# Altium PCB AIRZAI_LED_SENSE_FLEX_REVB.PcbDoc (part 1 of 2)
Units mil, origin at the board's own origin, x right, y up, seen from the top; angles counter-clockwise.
Board outline 2713.44 x 4393.69 mil, 2 copper layers (Top Layer, Bottom Layer); 53 components, 36 nets, 162 pads, 79 vias.
Unrouted connection lines stored in the file: 83.
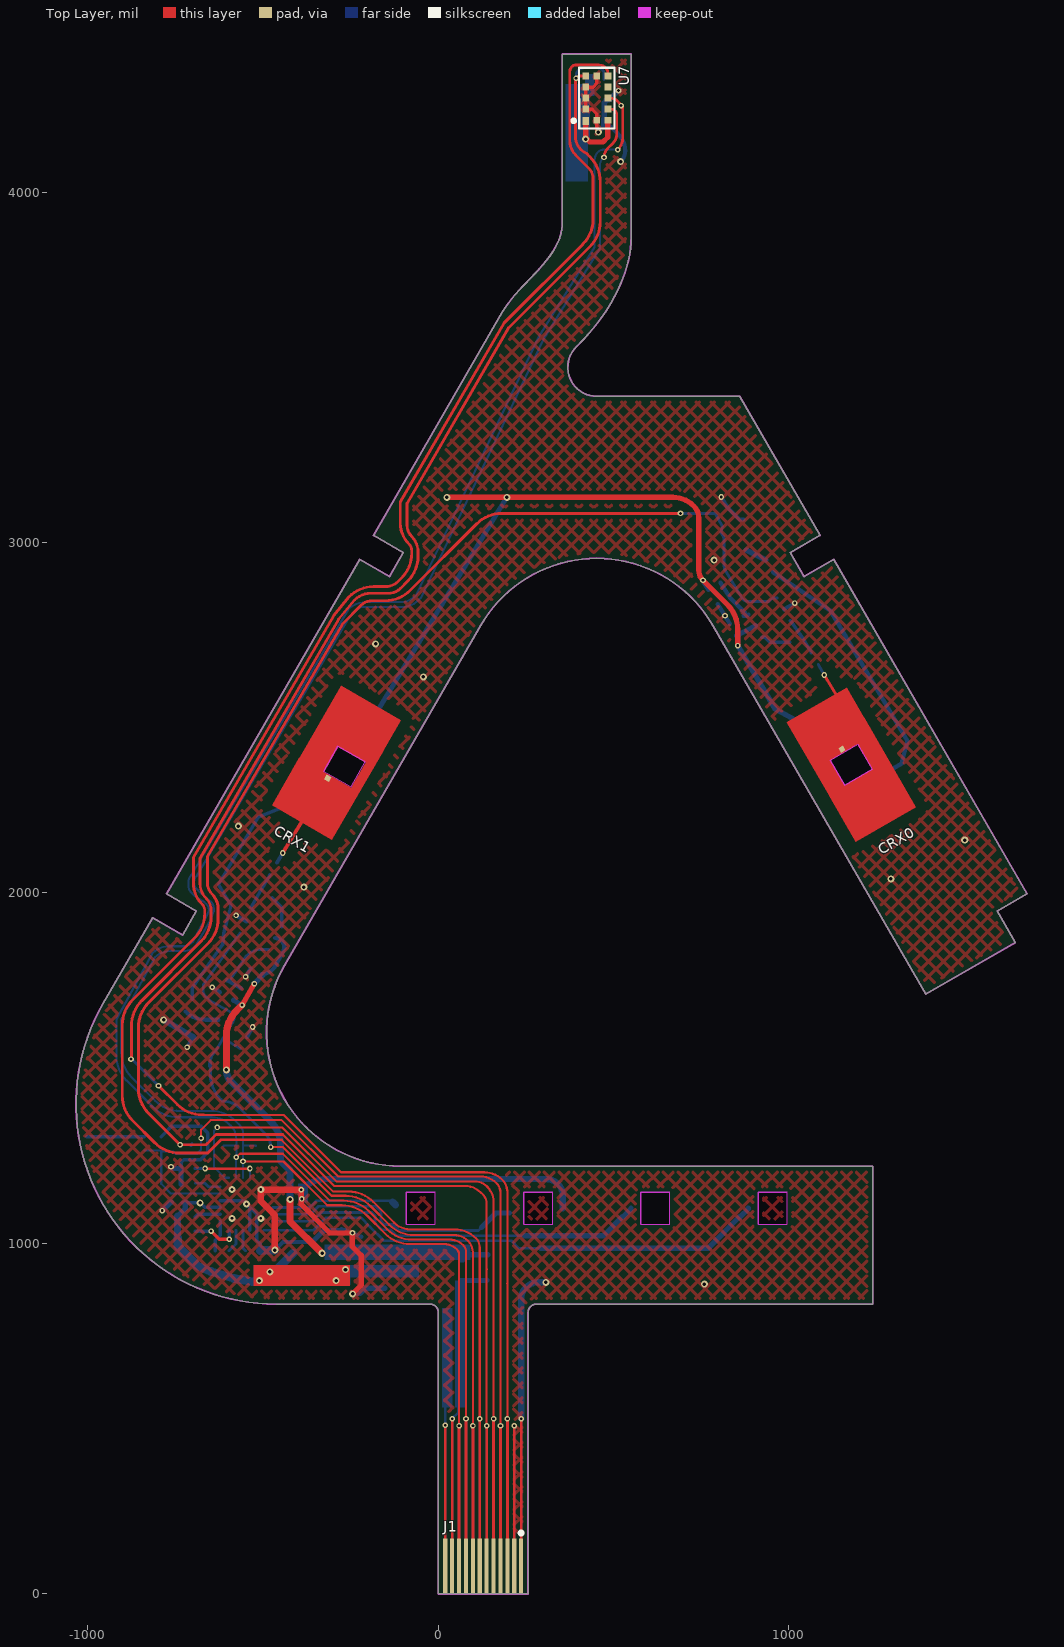
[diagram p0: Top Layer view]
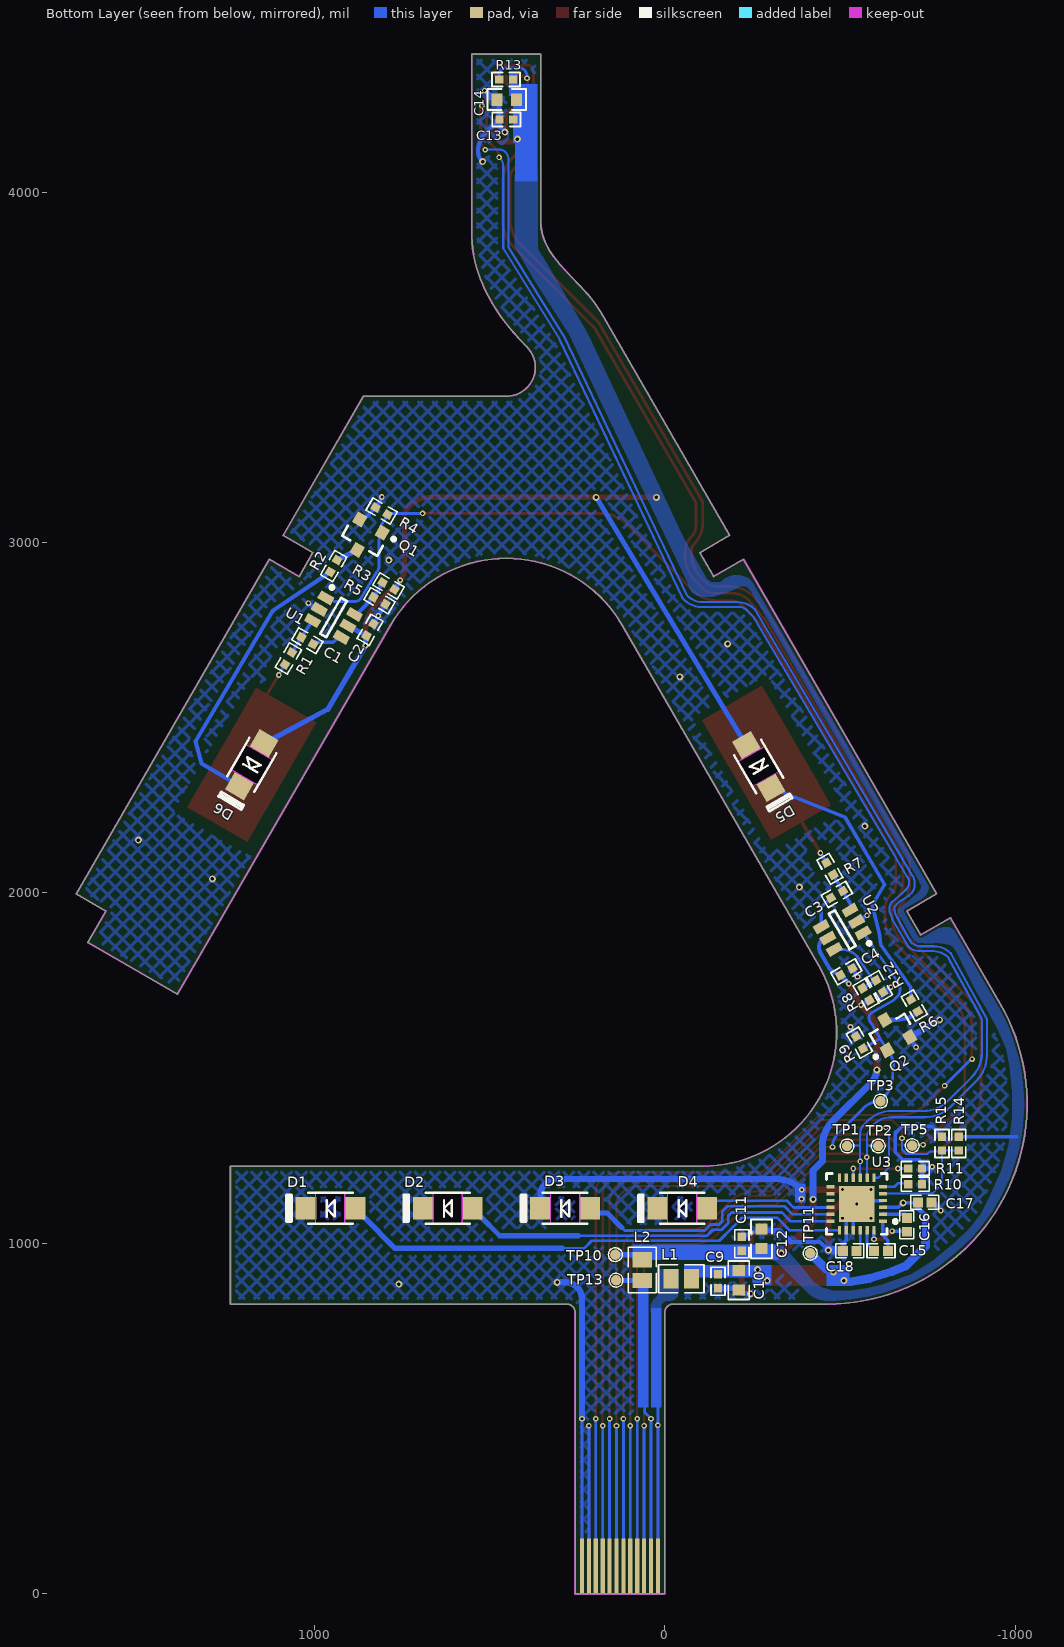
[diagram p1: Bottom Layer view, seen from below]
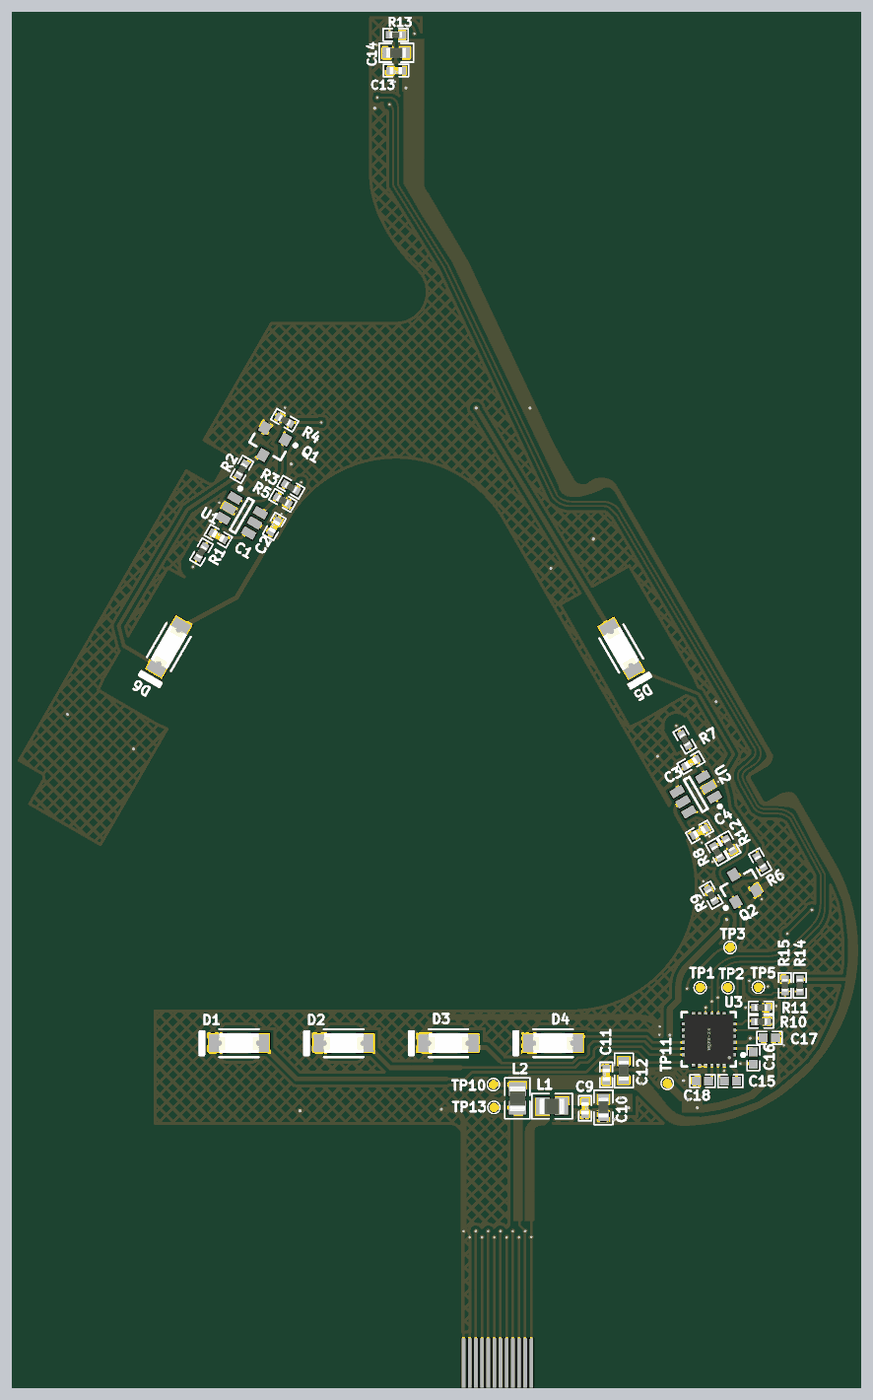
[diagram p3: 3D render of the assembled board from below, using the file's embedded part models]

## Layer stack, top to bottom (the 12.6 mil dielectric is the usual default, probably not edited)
Top Solder: solder mask 0.4, Solder Resist, Dk 3.5
Top Layer: signal copper 1.4
Dielectric 1: dielectric 12.6, FR-4, Dk 4.8
Bottom Layer: signal copper 1.4
Bottom Solder: solder mask 0.4, Solder Resist, Dk 3.5

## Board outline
-463,826.78 cw(c-462.98,1397.65) -957.36,1683.09 -815.14,1929.41 -729.91,1880.19 -690.53,1948.38 -775.77,1997.6 -224.58,2952.23 -139.35,2903.01 -99.97,2971.2 -185.21,3020.41 182.62,3657.47 cw(c465.09,3488.64) 220.1,3708.36 cw(c839.65,3165.01) 242.17,3732.54 264.96,3756.39 ccw(c-627.68,4615.35) 287.35,3780.27 ccw(c-93.59,4128.16) 308.19,3804.57 ccw(c73.79,3993.55) 326.37,3829.65 ccw(c158.18,3938.86) 340.75,3855.9 ccw(c204.05,3917.92) 350.2,3883.68 ccw(c222.06,3913.41) 353.61,3913.38 353.61,3952.75 353.61,4393.69 550.46,4393.69 550.46,3952.74 550.46,3874 cw(c239.31,3875.17) 542.24,3804.11 cw(c183.5,3887.15) 532.52,3769.79 cw(c138.88,3902.12) 519.55,3736.13 cw(c91.77,3922.61) 503.7,3703.33 cw(c24.31,3959.43) 464.84,3641.1 cw(c-49.74,4012.89) 394.16,3559.04 ccw(c452.02,3499.99) 452.02,3417.31 860.08,3417.3 1089.23,3020.38 1003.99,2971.17 1043.36,2902.98 1128.6,2952.19 1679.74,1997.53 1594.5,1948.32 1646.29,1858.61 1390.38,1711.31 782.73,2763.85 ccw(c452,2572.92) 121.28,2763.87 -439.1,1793.32 ccw(c-108.38,1602.36) -108.39,1220.47 1239.37,1220.44 1239.37,826.77 279.66,826.77 ccw(c279.78,802.89) 255.91,802.77 255.91,0 0,0 0,802.41 ccw(c-23.88,802.89) -23.39,826.77
cut-out: 912.59,1055.11 995.26,1055.11 995.26,1145.66 912.59,1145.66
cut-out: 577.94,1055.12 660.62,1055.12 660.62,1145.67 577.94,1145.67
cut-out: 243.3,1055.12 325.97,1055.12 325.97,1145.67 243.3,1145.67
cut-out: -91.36,1055.12 -8.68,1055.12 -8.68,1145.67 -91.36,1145.67
cut-out: 1159.59,2307.55 1118.49,2378.93 1196.97,2424.11 1238.06,2352.73
cut-out: -327.65,2347.93 -249.18,2302.74 -208.08,2374.12 -286.55,2419.3

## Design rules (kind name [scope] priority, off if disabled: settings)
Clearance Clearance_Board_Cutout_Electrodes [(InComponent('CRX0') OR InComponent('CRX1')) vs OnLayer('Multi-Layer')] p1: gap=0 ignorepadtopadclearanceinfootprint=FALSE
Clearance Clearance_Board_Cutout_Diodes [(InComponent('D1') OR InComponent('D2') OR InComponent('D3') OR InComponent('D4') OR InComponent('D5') OR InComponent('D6')) vs OnLayer('Multi-Layer')] p2: gap=0 ignorepadtopadclearanceinfootprint=FALSE
Clearance Clearance_Keepout [(OnLayer('Keep-Out Layer')) vs (InComponent('D1') OR InComponent('D2') OR InComponent('D3') OR InComponent('D4') OR InComponent('D5') OR InComponent('D6') OR InComponent('CRX0') OR InComponent('CRX1') OR InComponent('J1'))] p3: gap=0 ignorepadtopadclearanceinfootprint=FALSE
Clearance Clearance_GND_POLY_ELECTRODE [(InComponent('CRX0') OR InComponent('CRX1') OR InComponent('CRX2') OR InNet('NetCRX0_1') OR InNet('NetCRX1_1') OR InNet('NetCRX2_1') OR InNet('NetR4_2') OR InNet('NetR2_1') OR InNet('NetR1_1')) vs (InNet('GND') AND InPolygon)] p4: gap=30 ignorepadtopadclearanceinfootprint=FALSE
Clearance Clearance_POLYGON_KEEPOUT [(OnLayer('Keep-Out Layer')) vs (InNet('GND') AND InPolygon)] p5: gap=10 ignorepadtopadclearanceinfootprint=FALSE
Clearance Clearance_GND_POLY_REST [All vs (InNet('GND') AND InPolygon)] p6: gap=10 ignorepadtopadclearanceinfootprint=FALSE
Clearance [All] p7: gap=6 ignorepadtopadclearanceinfootprint=FALSE
MinimumSolderMaskSliver [All] p1: minsoldermaskwidth=1
PolygonConnect [All] p1: connectstyle=Direct reliefconductorwidth=10 reliefentries=4 polygonreliefangle="90 Angle" airgapwidth=10
RoomDefinition AIRZAI_LED_SENSE_FLEX_REVB [InComponentClass('AIRZAI_LED_SENSE_FLEX_REVB')] p1: confinementstyle=ConfineIn formatcopy=TRUE lockcomponents=FALSE outline -3892.14,-2713.97 10767.86,-2713.97 10767.86,6886.03 -3892.14,6886.03
RoutingVias [All] p1: holewidth=28 width=50 viastyle="Through Hole" minholewidth=8 minwidth=16 maxholewidth=28 maxwidth=50
SilkToSilkClearance [All] p1: silktosilkclearance=1
SilkToSolderMaskClearance [IsPad] p1: minsilkscreentomaskgap=2 clearancetoexposedcopper=TRUE
SolderMaskExpansion [All] p1: expansion=4
UnRoutedNet [All] p1: checkbadconnections=TRUE
Width [All] p1: maxlimit=100 minlimit=6 preferedwidth=10
26 further rules are at their usual default settings.

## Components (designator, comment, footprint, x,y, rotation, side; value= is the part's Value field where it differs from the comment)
C1 "22nF" 0402CAP 1020,2720 r210 bottom
C2 "0.1µF" 0402CAP 841,2751 r120 bottom
C3 "22nF" 0402CAP -491,1996 r330 bottom
C4 "0.1µF" 0402CAP -518.16,1775.08 r150 bottom
C9 "0.1µF" 0402CAP -152,892.17 r270 bottom
C10 "10µF" 0603 -211,895 r270 bottom
C11 "0.1µF" 0402CAP -220,999.22 r90 bottom
C12 "10µF" 0603 -276,1013 r90 bottom
C13 "0.1µF" 0402CAP 452.01,4207.25 r0 bottom
C14 "4.7µF" 0603 451,4264 r180 bottom
C15 "CAP 1uF 16V 0402(1005)" CAPC0402(1005)60_M -616.69,979 r0 bottom value=1uF
C16 "CAP 1uF 16V 0402(1005)" CAPC0402(1005)60_M -690.55,1053.06 r270 bottom value=1uF
C17 "CAP 1uF 16V 0402(1005)" CAPC0402(1005)60_M -741.73,1117.23 r0 bottom value=1uF
C18 "CAP 1uF 16V 0402(1005)" CAPC0402(1005)60_M -527.69,979 r0 bottom value=1uF
CRX0 "CONTACT POINT 1" "CONTACT_POINT_1CM _SQ - duplicate" 1178.28,2365.83 r300 top
CRX1 "CONTACT POINT 1" "CONTACT_POINT_1CM _SQ" -290.35,2372.21 r60 top
D1 "WHITE" LED1206_LTW-C230DS 953.93,1100.39 r0 bottom locked
D2 "WHITE" LED1206_LTW-C230DS 619.28,1100.4 r0 bottom locked
D3 "WHITE" LED1206_LTW-C230DS 284.63,1100.41 r0 bottom locked
D4 "WHITE" LED1206_LTW-C230DS -50.03,1100.42 r0 bottom
D5 "WHITE" LED1206_LTW-C230DS -267.86,2361.02 r240 bottom
D6 "WHITE" LED1206_LTW-C230DS 1178.28,2365.83 r300 bottom
J1 "FFC Pads" FFC_PADS 127.95,78.74 r0 top locked
L1 "CB2012T100KR" 0805 -47,899 r180 bottom value=10uH
L2 "CB2012T100KR" 0805 64,924 r90 bottom value=10uH
Q1 "NTR4003NT1G" SOT-23-3-NTR4003NT1G 858,3013 r300 bottom
Q2 "NTR4003NT1G" SOT-23-3-NTR4003NT1G -647,1604 r60 bottom
R1 "10k 0402(1005)" 0402 1074,2669 r300 bottom value=10k
R2 "100R 0402(1005)" 0402 944.64,2933 r300 bottom value=100
R3 "Jumper 0402(1005)" 0402 788.11,2876 r210 bottom value=0R
R4 "DNP 0402(1005)" 0402 808,3090 r30 bottom value=DNP
R5 "DNP 0402(1005)" 0402 814,2834 r210 bottom value=DNP
R6 "100R 0402(1005)" 0402 -712,1679.08 r60 bottom value=100
R7 "10k 0402(1005)" 0402 -471,2069 r60 bottom value=10k
R8 "Jumper 0402(1005)" 0402 -574.02,1711 r240 bottom value=0R
R9 "DNP 0402(1005)" 0402 -555.51,1573 r60 bottom value=DNP
R10 "Jumper 0402(1005)" 0402 -714.57,1168.99 r0 bottom value=0R
R11 "Jumper 0402(1005)" 0402 -714.57,1213.99 r0 bottom value=0R
R12 "DNP 0402(1005)" 0402 -613,1734 r240 bottom value=DNP
R13 "10k 0402(1005)" 0402 453,4321 r0 bottom value=10k
R14 "Jumper 0402(1005)" 0402 -838.76,1285 r270 bottom value=0R
R15 "DNP 0402(1005)" 0402 -790.88,1285 r90 bottom value=DNP
TP1 "Test Point" TP_0.9MM -520.09,1278 r90 bottom
TP2 "Test Point" TP_0.9MM -608.92,1278 r90 bottom
TP3 "Test Point" TP_0.9MM -615.68,1406 r90 bottom
TP5 "Test Point" TP_0.9MM -706,1279 r90 bottom
TP10 "Test Point" TP_0.9MM 141,968 r90 bottom
TP11 "Test Point" TP_0.9MM -415,972 r90 bottom
TP13 "Test Point" TP_0.9MM 139,895 r90 bottom
U1 "AT42QT1010-TSHR" SOT-23-6-AT42QT1010-TSHR 944.94,2785.89 r210 bottom
U2 "AT42QT1010-TSHR" SOT-23-6-AT42QT1010-TSHR -506.3,1895 r330 bottom
U3 "LP55231SQE/NOPB" WQFN-24-LP55231SQE/NOPB -547.74,1112.61 r0 bottom value="IC LED DRIVER RGLTR DIM 24WQFN"
U7 "VL53L0CXV0DH/1" VL53L0X 452,4268 r270 top

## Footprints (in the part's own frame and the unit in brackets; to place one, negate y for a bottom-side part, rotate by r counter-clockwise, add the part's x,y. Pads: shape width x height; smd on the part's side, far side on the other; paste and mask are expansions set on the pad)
0402 [mm] "Chip Resistor, Body 1.1x0.5mm, IPC High Density"
  rect 0.6x0.6 smd: 1(-0.5,0) 2(0.5,0)
  silkscreen extent -1.02,-0.51 1.02,0.51, body extent -0.5,-0.25 0.5,0.25, height 0.27
0402CAP [mm] "Chip Capacitor, Body 1.1x0.5mm, IPC High Density"
  rect 0.6x0.6 smd: 1(-0.5,0) 2(0.5,0)
  silkscreen extent -1.02,-0.51 1.02,0.51, body extent -0.5,-0.3 0.5,0.3, height 0.19
0603 [mm] "Chip Resistor, Body 1.6x0.8mm, IPC High Density"
  rect 0.8x0.9 smd: 1(-0.7,0) 2(0.7,0)
  silkscreen extent -1.4,-0.76 1.4,0.76, body extent -0.8,-0.41 0.8,0.4, height 0.37
0805 [mm] "Chip Resistor, Body 2.0x1.3mm, IPC High Density"
  rect 1.1x1.4 smd: 1(-0.75,0) 2(0.75,0)
  silkscreen extent -1.65,-1.02 1.65,1.02, body extent -1.02,-0.64 0.98,0.62, height 0.47
CAPC0402(1005)60_M [mm] "Chip Capacitor, Body 1.0x0.5mm, Height 0.6mm, IPC Low Density"
  rect 0.72x0.72 smd: 1(-0.5,0) 2(0.5,0)
  silkscreen extent -1.02,-0.51 1.02,0.51, body extent -0.55,-0.3 0.55,0.3, height 0.6
"CONTACT_POINT_1CM _SQ" [mm]
  rect 0.4x0.4 smd paste-2 mask-2: 1(-1.312,-0.018)
  Top Layer region: -3.216,2.5 -1.068,0.472 1.05,0.472 1.05,-2.5 5,-2.5 5,2.5
  Top Layer region: 2.48,-2.5 1.768,-1.828 -1.05,-1.828 -1.05,2.5 -5,2.5 -5,-2.5
"CONTACT_POINT_1CM _SQ - duplicate" [mm]
  rect 0.4x0.4 smd paste-2 mask-2: 1(-1.312,-0.018)
  Top Layer region: 2.48,-2.5 1.05,-1.15 -1.05,-1.15 -1.05,2.5 -5,2.5 -5,-2.5
  Top Layer region: -2.48,2.5 -1.05,1.15 1.05,1.15 1.05,-2.5 5,-2.5 5,2.5
FFC_PADS [mm] "(0.50mm"
  rect 0.3x4 smd: 1(2.75,0) 2(2.25,0) 3(1.75,0) 4(1.25,0) 5(0.75,0) 6(0.25,0) 7(-0.25,0) 8(-0.75,0) 9(-1.25,0) 10(-1.75,0) 11(-2.25,0) 12(-2.75,0)
  rect 0.3x4 smd far side: 1(2.75,0) 2(2.25,0) 3(1.75,0) 4(1.25,0) 5(0.75,0) 6(0.25,0) 7(-0.25,0) 8(-0.75,0) 9(-1.25,0) 10(-1.75,0) 11(-2.25,0) 12(-2.75,0)
  silkscreen extent 2.63,2.29 2.87,2.54
LED1206_LTW-C230DS [mm] "Chip Capacitor, Body 3.2x1.6mm, IPC High Density"
  rect 1.5x1.6 smd paste-0.1 mask+0.07: 1(1.775,0) 2(-1.775,0)
  silkscreen extent -1.6,-1.13 3.19,1.13, body extent -1.63,-0.8 1.63,0.8, height 0.31
SOT-23-3-NTR4003NT1G [mm] "SOT23, 3-Leads, Body 2.92x1.3mm, Pitch 0.95mm"
  rect 0.9x0.8 smd: 1(-1,0.95) 2(-1,-0.95) 3(1,0)
  silkscreen extent -1.12,-1.46 0.65,2.02, body extent -0.65,-1.46 0.65,1.46, height 1.11
SOT-23-6-AT42QT1010-TSHR [mm] "SOT23, 6-Leads, Body 2.9x1.6mm, Pitch 0.95mm, Lead Span 2.8mm, IPC Medium Density"
  rect 1.1x0.65 smd: 1(-1.2,0.95) 2(-1.2,0) 3(-1.2,-0.95) 4(1.2,-0.95) 5(1.2,0) 6(1.2,0.95)
  silkscreen extent -1.32,-1.5 0.25,1.95, body extent -0.88,-1.5 0.88,1.5, height 1.45
TP_0.9MM [mm] "0.9MM DIA TESTPOINT"
  round 0.75 smd paste-5 mask+0.05: 1(0,0)
  silkscreen extent -0.5,-0.5 0.5,0.5
VL53L0X [mm]
  rect 0.58x0.5 smd: 1(1.64,-0.8)
  rect 0.5x0.5 smd: 2(0.8,-0.8) 3(0,-0.8) 4(-0.8,-0.8) 5(-1.6,-0.8) 6(-1.6,0) 7(-1.6,0.8) 8(-0.8,0.8) 9(0,0.8) 10(0.8,0.8) 11(1.6,0.8) 12(1.6,0)
  silkscreen extent -2.2,-1.79 2.2,1.3, body extent -2.2,-1.3 2.2,1.3, height 3.72
WQFN-24-LP55231SQE/NOPB [mm] "QFN, 24-Leads, Body 3.97x3.97mm, Pitch 0.50mm, Thermal Pad 2.60x2.60mm, IPC Medium Density"
  rect 0.6x0.25 smd: 1(-1.9,1.25) 2(-1.9,0.75) 3(-1.9,0.25) 4(-1.9,-0.25) 5(-1.9,-0.75) 6(-1.9,-1.25) 13(1.9,-1.25) 14(1.9,-0.75) 15(1.9,-0.25) 16(1.9,0.25) 17(1.9,0.75) 18(1.9,1.25)
  rect 0.25x0.6 smd: 7(-1.25,-1.9) 8(-0.75,-1.9) 9(-0.25,-1.9) 10(0.25,-1.9) 11(0.75,-1.9) 12(1.25,-1.9) 19(1.25,1.9) 20(0.75,1.9) 21(0.25,1.9) 22(-0.25,1.9) 23(-0.75,1.9) 24(-1.25,1.9)
  rect 2.6x2.6 smd: 25(0,0)
  silkscreen extent -2.92,-2.2 2.2,2.2, body extent -2.01,-2.01 2.01,2.01, height 0.8

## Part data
C1 C3: library part C0402-100n, "Capacitor, X7R, ±10%", Case/Package=0402, Case Code (Metric)=1005, Dielectric=X7R, Manufacturer=TDK, Manufacturer Part Number=CGA2B2X7R1E223K050BA, Max Operating Temperature=125°C, Min Operating Temperature=-55°C, Package Quantity=1, Ratings=AEC-Q200, Supplier Part Number 1=445-5609-1-ND, Tolerance=10%, Voltage Rating=25V
C2 C4 C9 C11 C13: library part C0402-100n, "Capacitor, X7R, ±10%", Case-EIA=0402, Case-Metric=1005, Manufacturer=TDK, Manufacturer Part Number=C1005X7R1C104K, Rated Voltage="16 V", Supplier Part Number 1=445-4952-2-ND, Tolerance=±20%
C10 C12: library part C0402-100n, "Capacitor, X7R, ±10%", Case-EIA=0603, Case-Metric=1608, Manufacturer=MURATA, Manufacturer Part Number=GRM188R60J106ME47D, Rated Voltage="6.3 V", Supplier Part Number 1=490-3896-6-ND, Tolerance=±20%
C14: library part "C0603-1µ0 X7R", "Capacitor, X7R, ±10%", Case-EIA=0402, Case-Metric=1005, Manufacturer=TDK, Manufacturer Part Number=C1005X5R0J475M, Rated Voltage="6.3 V", Supplier Part Number 1=445-7395-2-ND, Tolerance=±20%
C15 C16 C17 C18: library part CAP, "CAP 1uF 16V ±10% 0402 (1005 Metric) Thickness 0.6mm SMD", Case-EIA=0402, Case-Metric=1005, Manufacturer="Taiyo Yuden", Manufacturer Part Number=JMK105C6105KV-F, Rated Voltage="6.3 V", Supplier Part Number 1=587-3381-1-ND, Tolerance=±10%
CRX0 CRX1: library part WIRE_POINT
D1 D2 D3 D4 D5 D6: library part LED_LTW-C230DS, Case-EIA=1206, Case-Metric=3216, Manufacturer=LITEON, Manufacturer Part Number=LTW-C230DS, Supplier Part Number 1=160-2221-1-ND
J1: library part FFC_PADS, "0.5 mm Pitch FFC Pads"
L1 L2: "Inductor, 10 µH, 0.5A, 0.65 ohm, SMD", Case/Package=0805, Case Code (Metric)=2012, Current Rating=520mA, DC Resistance (DCR)=500mR, Inductance=10uH, Inductance Tolerance=10%, Manufacturer="Taiyo Yuden", Max DC Current=200mA, Max Operating Temperature=105°C, Min Operating Temperature=-40°C, Package Quantity=3000, Self Resonant Frequency=32MHz, Supplier Part Number 1=587-2452-1-ND, Test Frequency=2.52MHz, Value1="0.65 ohm", Value2=0.5A, ValueDisplayed=10µH
Q1 Q2: "N-Channel 30V 500mA (Ta) 690mW (Ta) Surface Mount SOT-23-3 (TO-236)", Case/Package=SOT-23-3, Continuous Drain Current (ID)=500mA, Drain to Source Breakdown Voltage=30V, Drain to Source Resistance=1R, Gate to Source Voltage (Vgs)=20V, Input Capacitance=21pF, Manufacturer="ON Semiconductor", Max Operating Temperature=150°C, Max Power Dissipation=690mW, Min Operating Temperature=-55°C, Package Quantity=1, Supplier Part Number 1=NTR4003NT1GOSCT-ND, Threshold Voltage=1.4V
R1 R7 R13: library part RES, "10k 0.063W 1% 0402 (1005 Metric)  SMD", Case-EIA=0402, Case-Metric=1005, Manufacturer=Yageo, Manufacturer Part Number=RC0402FR-0710KL, Power=0.063W, Supplier Part Number 1=311-10.0KLRCT-ND, Tolerance=None
R2 R6: library part RES, "100 0.063W 1% 0402 (1005 Metric)  SMD", Case-EIA=0402, Case-Metric=1005, Manufacturer=Yageo, Manufacturer Part Number=RC0402FR-07100RL, Power=None, Supplier Part Number 1=311-100LRCT-ND
R3 R8 R10 R11 R14: library part RES, "Jumper 0402 (1005 Metric)", Case-EIA=0402, Case-Metric=1005, Manufacturer=Panasonic, Manufacturer Part Number=ERJ-2GE0R00X, Power=None, Supplier Part Number 1=P0.0JCT-ND
R4 R5 R9 R12 R15: library part RES, "DNP", Case-EIA=0402, Case-Metric=1005, Power="0.0625 W", Tolerance=None
U1 U2: "One-channel Touch Sensor IC with Reset Timer, -40° to +85° C, 6-pin SOT23", Supplier Part Number 1=AT42QT1010-TSHRCT-ND
U3: "Imported", Case-EIA=24-WQFN, Manufacturer=TI, Supplier Part Number 1=296-39059-1-ND, Tolerance=None
U7: library part VL53L0X, Case-EIA=LGA12, Manufacturer=ST, Supplier Part Number 1=497-16538-1-ND, Tolerance=None

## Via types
v1: diameter 16, hole 8, Top Layer to Bottom Layer, tented both sides, 49 vias
v2: diameter 20, hole 10, Top Layer to Bottom Layer, tented both sides, 25 vias
v3: diameter 20, hole 8, Top Layer to Bottom Layer, 5 vias

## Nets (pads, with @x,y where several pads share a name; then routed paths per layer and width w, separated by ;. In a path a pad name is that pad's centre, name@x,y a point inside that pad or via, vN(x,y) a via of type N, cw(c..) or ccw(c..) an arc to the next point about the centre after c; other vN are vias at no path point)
3V3: C2.1 C4.1 C11.1 C12.1 C13.1 C14.2 D5.2 D6.2 L2.2 R3.2 R8.2 R13.1 R14.1 TP10.1 U1.5 U2.5 U7.1 U7.11 | length 4046.3
  Top Layer w15: v1(-560,1680) v1(-525.05,1741) ; v2(24,3129) 668.64,3129 cw(c668.64,3043.64) 729,3104 cw(c695.2,3070.2) 743,3070.2 743,2921.23 ccw(c783.97,2921.23) v1(755,2892.26) 824.71,2822.55 cw(c754,2751.84) 854,2751.84 v1(854,2706) ; U7.1@420.5,4203.43 v2(420.5,4151.32) 423.68,4151.32 432,4143 470,4143 483.5,4156.5 U7.11@483.5,4201.86
  Top Layer w20: v2(-605,1495) -605,1593.58 cw(c-505,1593.58) -575.71,1664.29 v1(-560,1680) ; v2(-423,1126) -423,1063 v2(-332,972)
  Bottom Layer w10: -1004,1305 -999,1305 -998.69,1304.69 R14.1@-838.76,1304.69
  Bottom Layer w12: C4.1@-504.11,1768.24 ccw(c-504.11,1810.11) -474.5,1780.5 -469,1786 -443,1831.47 -440,1842 -440,1845.99 ccw(c-465.39,1845.99) U2.5@-465.39,1871.38
  Bottom Layer w15: R8.2@-583.86,1693.95 v1(-560,1680) ; v1(-525.05,1741) -525.05,1741.65 -501.34,1765.36 C4.1@-501,1766 ; D5.2@-232.92,2421.54 v2(195.72,3129.17) ; L2.2@64,953.53 69.91,953.53 84.38,968 TP10.1@141,968 ; v1(755,2892.26) R3.2@771.06,2866.16 ; U1.5@904.03,2762.27 C2.1@850.84,2733.95 854,2730.79 v1(854,2706) 962,2524 D6.2@1143.34,2426.35
  Bottom Layer w20: v2(-605,1495) ccw(c-556.72,1495) -590.86,1460.86 -479.29,1349.29 cw(c-550,1278.58) -450,1278.58 -450,1235.77 -422.69,1208.46 -422.69,1126.31 v2(-423,1126)
+5V: C9.1 C10.1 C17.2 L1.2 TP11.1 U3.3 | length 634.2
  Bottom Layer w10: C17.2@-730.32,1115.77 -722.05,1115.77 -679.74,1115.77 -666.74,1102.77 U3.3@-622.54,1102.77
  Bottom Layer w15: -744.8,994.83 -743.8,993.83 ; -743.8,1078.55 -722.05,1100.3 -722.05,1115.77 C17.2@-722.05,1117.23
  Bottom Layer w20: -743.8,1016.44 -743.8,1078.55
  Bottom Layer w25: -743.8,1016.44 -743.8,993.83 -743.8,992.27 -686.76,935.24 -649,920 -583.14,900 -530,891 -477,892 ; v2(-481,919) -481,920 -474.5,926.5 -460.5,926.5 TP11.1@-415,972
  other v2: -511,894 -292,894 -265,925 -680.02,1116.05
CAP1_TOUCH_OUT: J1.6 Q1.1 R4.1 TP5.1 U1.1 | length 5736.1
  Top Layer w6: -444,1311 -297,1164 76,1164 cw(c76,1101.23) 120.38,1145.62 129,1137 cw(c107.77,1115.77) 137.8,1115.77 137.8,926.29 ; v1(137.8,480) 137.8,926.29 ; 138,926.5 137.8,926.29
  Top Layer w8: -444,1311 -634,1311 -652,1293 -652,1292.54 -662.94,1281.6 v1(-737,1281.6) -826.71,1371.31 cw(c-756,1442.02) -856,1442.02 -856,1616.15 cw(c-756,1616.15) -826.71,1686.86 -657.74,1855.84 ccw(c-728.45,1926.55) -628.45,1926.55 -628.45,1954.63 ccw(c-688.37,1954.63) -646,1997 cw(c-614.62,2028.38) -659,2028.38 -659,2103 -273.55,2767.9 -220.49,2820.96 cw(c-189,2789.47) -189,2834 -151.47,2834 ccw(c-151.47,2934) -80.76,2863.29 109.66,3053.71 cw(c180.37,2983) 180.37,3083 v1(691,3083) ; J1.6@137.8,78.74 v1(137.8,480)
  Bottom Layer w8: v1(-737,1281.6) -707.18,1281.6 -703.32,1285.47 cw(c-712.47,1285.47) TP5.1@-706,1279 ; J1.6@137.8,78.74 v1(137.8,480) ; v1(691,3083) 788.11,3083 R4.1@790.95,3080.16 810.66,3047.11 Q1.1@805.92,3028.39 cw(c783.19,3005.66) 815.34,3005.66 815.34,2932.03 ccw(c838.08,2932.03) 822,2915.95 869,2838.08 ccw(c883.39,2852.47) 883.39,2832.12 943.67,2832.12 953.46,2841.91 U1.1@967.16,2841.91
CAP2_TOUCH_OUT: J1.8 Q2.1 R9.1 TP3.1 U2.1 | length 2854.2
  Top Layer w6: v1(-478.49,1275) -443.97,1275 -304.97,1136 -264.42,1136 cw(c-264.42,1036) -193.71,1106.71 -140.29,1053.29 ccw(c-69.58,1124) -69.58,1024 43.96,1024 cw(c43.96,965.96) 85,1007 cw(c52.59,974.59) 98.43,974.59 98.43,929.43 ; v1(98.43,480) 98.43,929.43 ; 99,930 98.43,929.43
  Top Layer w8: J1.8@98.43,78.74 v1(98.43,480)
  Bottom Layer w8: -653.32,1505.27 cw(c-588.36,1505.27) Q2.1@-634.29,1551.2 -613.96,1586 ; -650.32,1517.27 -650.32,1482.06 ccw(c-550.32,1482.06) -621.03,1411.35 TP3.1@-615.68,1406 cw(c-615.68,1336) -566.18,1385.5 -494.6,1313.92 cw(c-533.56,1275) v1(-478.49,1275) ; U2.1@-565.92,1886.23 -671.14,1738 -671,1737.86 -671,1721.15 ccw(c-648.74,1721.15) -664.48,1705.41 -653.32,1694.25 -590,1658 -586.91,1654.91 cw(c-596.81,1645) -582.8,1645 -582.8,1644.37 cw(c-607.37,1644.37) -590,1627 -613.96,1586 ; R9.1@-565.36,1555.95 -613.96,1586 ; J1.8@98.43,78.74 v1(98.43,480)
EN: J1.4 R14.2 R15.1 U3.5 | length 2926.6
  Top Layer w6: v1(-677,1300) -677,1324.55 -649.55,1352 -447.08,1352 -286.08,1191 120.13,1191 cw(c120.13,1126.13) 166,1172 cw(c139.44,1145.44) 177,1145.44 177,870.52 177.17,870.35 v1(177.17,480)
  Top Layer w8: J1.4@177.17,78.74 v1(177.17,480)
  Bottom Layer w6: R14.2@-838.76,1265.32 R15.1@-790.88,1265.32 ; v1(-677,1300) -677,1268 -689.76,1255.24 -748.92,1255.24 -755.69,1262 -787.57,1262 R15.1@-790.88,1265.32 ; U3.5@-622.54,1142.14 -762.98,1142.14 -790.88,1170.04 R15.1@-790.88,1265.32
  Bottom Layer w8: J1.4@177.17,78.74 v1(177.17,480)
GND: C2.2 C4.2 C9.2 C10.2 C11.2 C12.2 C13.2 C14.1 C17.1 C18.2 D1.1 D2.1 D3.1 D4.1 J1.1 J1.2 Q1.2 Q2.2 R4.2 R5.2 R9.2 R10.1 R11.1 R12.2 R15.2 U1.2 U2.2 U3.4 U3.20 U3.21 U3.25 U7.2 U7.3 U7.4 U7.6 U7.12 | length 5717.7
  Top Layer w8: J1.2@216.54,78.74 v1(216.54,480) ; J1.1@236.22,78.74 v1(236.22,499.74)
  Top Layer w10: U7.6@452,4330.99 452,4310 441.5,4299.5 U7.4@420.5,4299.5 U7.3@420.5,4268 U7.2@420.5,4236.5 439.49,4236.5 452,4223.99 U7.12@452,4205.01 452,4175.5 v2(456.5,4171)
  Top Layer w15: v1(-391,1153) -391,1111 -310,1030 v1(-245,1030) -245,1029.73 -246,1028.73 -246,992 -220,966 -220,881 v2(-245,856)
  Top Layer w18: v2(-466.69,980.83) -466.69,1081.06 -506.8,1121.17 v3(-506.8,1153.56) v1(-391,1153)
  Bottom Layer w8: J1.2@216.54,78.74 v1(216.54,480) ; J1.1@236.22,78.74 v1(236.22,499.74)
  Bottom Layer w10: R15.2@-790.88,1304.69 -761.57,1334 -677.2,1334 -658.2,1315 -658.2,1308.07 -658,1307.87 -658,1260 -678.75,1239.25 -726.89,1239.25 -734.14,1232 -734.14,1214.11 R11.1@-734.26,1213.99 ; U3.4@-622.54,1122.46 -557.58,1122.46 v3(-547.74,1112.61) U3.25@-537.9,1102.77 ; U3.21@-537.9,1037.81 U3.25@-537.9,1102.77 ; C18.2@-508,979 -508,999.14 -518.21,1009.35 U3.20@-518.21,1037.81 -518.21,1083.09 U3.25@-537.9,1102.77
  Bottom Layer w12: v1(-717,1560) Q2.2@-699.08,1588.61 ; v1(-645,1731) R12.2@-622.84,1716.95 ; v1(-577.27,1936) U2.2@-547.21,1918.62 ; v1(-550,1761) C4.2@-535.21,1784.92 ; R9.2@-545.67,1590.05 v1(-530.09,1617.64) ; v2(-466.69,980.83) -443.12,1004.39 -359.73,1004.39 ; C12.2@-276,1040.56 -265.44,1036.96 v1(-245,1030) C11.2@-220,1018.91 ; v2(456.5,4171) 469.96,4184.46 469.96,4205.51 C13.2@471.69,4207.25 512.54,4166.4 cw(c463.14,4117) 533,4117 cw(c491.96,4117) 520.98,4087.98 v2(520,4087) ; R5.2@796.95,2824.16 v1(817.84,2791) C2.2@831.16,2768.05 ; v1(807.11,3130) R4.2@825.05,3099.84 849.19,3075.7 849.29,3075.7 859.19,3065.8 Q1.2@870.71,3065.8 ; U1.2@985.86,2809.52 v1(1017,2827.11)
  Bottom Layer w15: v1(-787.69,1093.83) -764.28,1117.23 C17.1@-761.42,1117.23 ; v1(-762.98,1218.83) -758.14,1213.99 R11.1@-734.26,1213.99 R10.1@-734.26,1168.99 ; -359.73,1004.39 -327.16,1036.96 C12.2@-265.44,1036.96 ; v2(-245,856) -244.04,856.96 -223.45,856.96 C10.2@-212.97,867.44 ; C10.2@-211,867.44 C10.2@-212.97,867.44 ; C9.2@-152,872.48 -207.93,872.48 C10.2@-212.97,867.44 ; C13.2@471.69,4207.25 ccw(c468.53,4210.41) 473,4210.41 473,4255 476.13,4258.13 ccw(c470.25,4264) C14.1@478.56,4264 ; C14.1@487,4263 513.5,4289.5 v1(514,4289.5)
  Bottom Layer w18: v2(-784,1637.75) Q2.2@-699.08,1588.61 ; v1(-391,1153) -389.29,1154.71 cw(c-318.58,1084) -318.58,1184 305.79,1184 cw(c305.79,1132.79) 342,1169 cw(c311.79,1138.79) 354.51,1138.79 D3.1@354.51,1100.41 ; v1(236.22,499.74) 236.22,841.73 cw(c283.27,841.73) 250,875 cw(c283.8,841.2) 283.8,889 v2(307,889)
  Bottom Layer w25: C18.2@-508,979 -506.17,980.83 v2(-466.69,980.83)
  other v1: -390,1127
  other v2: 759,884 -384,2016.61 1291,2040 1502,2151 -571,2191 -43,2617 -179,2711 787,2950
  other v3: -588.69,1071.67 -506.8,1071.67 -588.69,1153.56
INT: J1.5 U3.7 | length 2520.1
  Top Layer w6: v1(-631,1331) -445.17,1331 -291.17,1177 103.91,1177 cw(c103.91,1127.37) 139,1162.46 cw(c94.38,1117.85) 157.48,1117.85 v1(157.48,499.74)
  Top Layer w8: J1.5@157.48,78.74 v1(157.48,499.74)
  Bottom Layer w6: v1(-631,1331) -640,1322 -640,1217.47 -609.95,1187.42 U3.7@-596.95,1187.42
  Bottom Layer w8: J1.5@157.48,78.74 v1(157.48,499.74)
NetC1_1: C1.1 R1.1 U1.3 | length 108.9
  Bottom Layer w10: U1.3@1004.56,2777.13 C1.1@1037.05,2729.84 R1.1@1064.16,2686.05
NetC1_2: C1.2 U1.4 | length 85.4
  Bottom Layer w10: U1.4@922.73,2729.88 931.4,2729.88 946.23,2715.05 C1.2@1002,2715.05
NetC3_1: C3.1 R7.1 U2.3 | length 117.9
  Bottom Layer w8: U2.3@-535,1958.68 U2.3@-528.51,1951.01
  Bottom Layer w10: U2.3@-535,1958.68 C3.1@-508.05,2005.84 R7.1@-480.84,2051.95
NetC3_2: C3.2 U2.4 | length 93.7
  Bottom Layer w10: C3.2@-473.95,1986.16 -446.68,1958.89 U2.4@-446.68,1903.77
NetC15_1: C15.1 U3.1 | length 90.1
  Bottom Layer w10: C15.1@-636.37,979 -636.37,1009.14 -622.54,1022.97 U3.1@-622.54,1063.4
NetC15_2: C15.2 U3.23 | length 67
  Bottom Layer w8: C15.2@-597,979 -577.27,998.73 U3.23@-577.27,1037.81
NetC16_1: C16.1 U3.2 | length 75.2
  Bottom Layer w10: C16.1@-694.28,1074.67 -685.87,1083.09 U3.2@-622.54,1083.09
NetC16_2: C16.2 U3.24 | length 135.8
  Top Layer w10: v1(-648.57,1035.3) -625.26,1011.99 v1(-596.95,1011.99) v1@-596.95,1008.99
  Bottom Layer w10: C16.2@-694.28,1035.3 v1(-648.57,1035.3) ; v1(-596.95,1011.99) U3.24@-596.95,1037.81
NetC18_1: C18.1 U3.22 | length 61.8
  Bottom Layer w8: U3.22@-557.58,1037.81 -557.58,986.21 C18.1@-550.37,979
NetCRX0_1: CRX0.1 R1.2 | length 269.4
  Top Layer w8: v1(1101,2622) 1174.17,2501.29 CRX0.1@1151.84,2410.24
  Bottom Layer w8: R1.2@1083.84,2651.95 v1(1101,2622)
NetCRX1_1: CRX1.1 R7.2 | length 281.6
  Top Layer w10: v1(-444,2114) CRX1.1@-315.53,2327.08
  Bottom Layer w10: R7.2@-461.16,2086.05 v1(-444,2114)
NetD1_2: D1.2 U3.19 | length 1482.2
  Bottom Layer w8: U3.19@-498.53,1037.81 -356.19,1037.81 -320.49,1073.51 -221.13,1073.51 -195,1047.38 -195,1047.2 -155.42,1007.62 208.38,1007.62 230,986 292,986
  Bottom Layer w15: 292,986 769.65,986 860.04,1076.4 862.01,1076.4 884.04,1098.43 D1.2@884.04,1100.39
NetD2_2: D2.2 U3.18 | length 1105.8
  Bottom Layer w8: U3.18@-472.94,1063.4 -358.6,1063.4 -334,1088 -190,1088 -181,1079 -181,1058 -162,1039 -137,1039 -120,1022 246,1022
  Bottom Layer w15: 246,1022 470.99,1022 525.4,1076.41 527.37,1076.41 549.39,1098.43 D2.2@549.39,1100.4
NetD3_2: D3.2 U3.17 | length 750.5
  Bottom Layer w8: U3.17@-472.94,1083.09 -364.91,1083.09 -342,1106 -179,1106 -164,1091 -164,1064 -154,1054 -130.22,1054 -113.22,1037 114.43,1037 123,1045.57
  Bottom Layer w15: 123,1045.57 164.17,1086.74 D3.2@203.05,1086.74
NetD4_2: D4.2 U3.16 | length 364.4
  Bottom Layer w8: U3.16@-472.94,1102.77 -367.23,1102.77 -348,1122 D4.2@-134.22,1122
  Bottom Layer w10: D4.2@-134.22,1122 D4.2@-130.22,1118
  Bottom Layer w20: D4.2@-130.22,1118 D4.2@-121.67,1109.46
NetD5_1: D5.1 R6.2 | length 818.2
  Bottom Layer w10: R6.2@-702.16,1696.13 -702.16,1729.84 -702,1730 -615.68,1853 -612,1886 -591.82,1963.83 -627,2023.63 -515,2216 D5.1@-302.8,2300.5
NetD6_1: D6.1 R2.2 | length 822.3
  Bottom Layer w12: R2.2@954.48,2915.95 1118.92,2805 1338.48,2433.56 1322.05,2369.65 D6.1@1213.22,2305.31
NetJ1_11: J1.11 L2.1 TP13.1 | length 997.2
  Top Layer w8: J1.11@39.37,78.74 v1(39.37,500)
  Bottom Layer w8: J1.11@39.37,78.74 v1(39.37,500) 39.37,500.37 57,518 57,571 56,570
  Bottom Layer w15: L2.1@64,894.47 TP13.1@139,895
NetJ1_12: J1.12 L1.1 | length 885.5
  Top Layer w8: J1.12@19.68,78.74 v1(19.68,481)
  Bottom Layer w8: J1.12@19.68,78.74 v1(19.68,481) 19.68,562
NetQ1_3: Q1.3 R2.1 | length 64
  Bottom Layer w15: Q1.3@877.69,2978.9 R2.1@934.8,2950.05
NetQ2_3: Q2.3 R6.1 | length 100.9
  Bottom Layer w12: R6.1@-721.84,1662.03 ccw(c-664.06,1719.82) -664.06,1638.1 Q2.3@-627.31,1638.1
NetR3_1: R3.1 R5.1 U1.6 | length 137.2
  Bottom Layer w12: R3.1@805.16,2885.84 R5.1@831.05,2843.84 874.32,2800.57 874.32,2794.61 870.71,2791 876.48,2791 ccw(c876.48,2803.51) U1.6@885.33,2794.66
NetR8_1: R8.1 R12.1 U2.6 | length 205
  Bottom Layer w8: R12.1@-603.06,1750.99 -594.1,1752.69 -548,1820.34 cw(c-502.98,1775.31) -502.98,1838.99 U2.6@-484.09,1838.99
  Bottom Layer w12: R12.1@-603.06,1750.99 R8.1@-564.17,1728.05
NetR10_2: R10.2 U3.6 | length 75.6
  Bottom Layer w8: R10.2@-694,1171.83 -665.41,1171.83 -655.41,1161.83 U3.6@-622.54,1161.83
NetR11_2: R11.2 U3.10 | length 186.4
  Top Layer w6: v1(-665.57,1213.74) -664.83,1212.99 v1@-538.9,1212.99
  Top Layer w8: v1@-538.9,1212.99 v1(-537.9,1213.99)
  Bottom Layer w6: U3.10@-537.9,1187.42 v1(-537.9,1213.99)
  Bottom Layer w8: R11.2@-694.89,1213.99 -665.83,1213.99 v1(-665.57,1213.74) ; v1(-537.9,1213.99) v1@-537.9,1215.99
